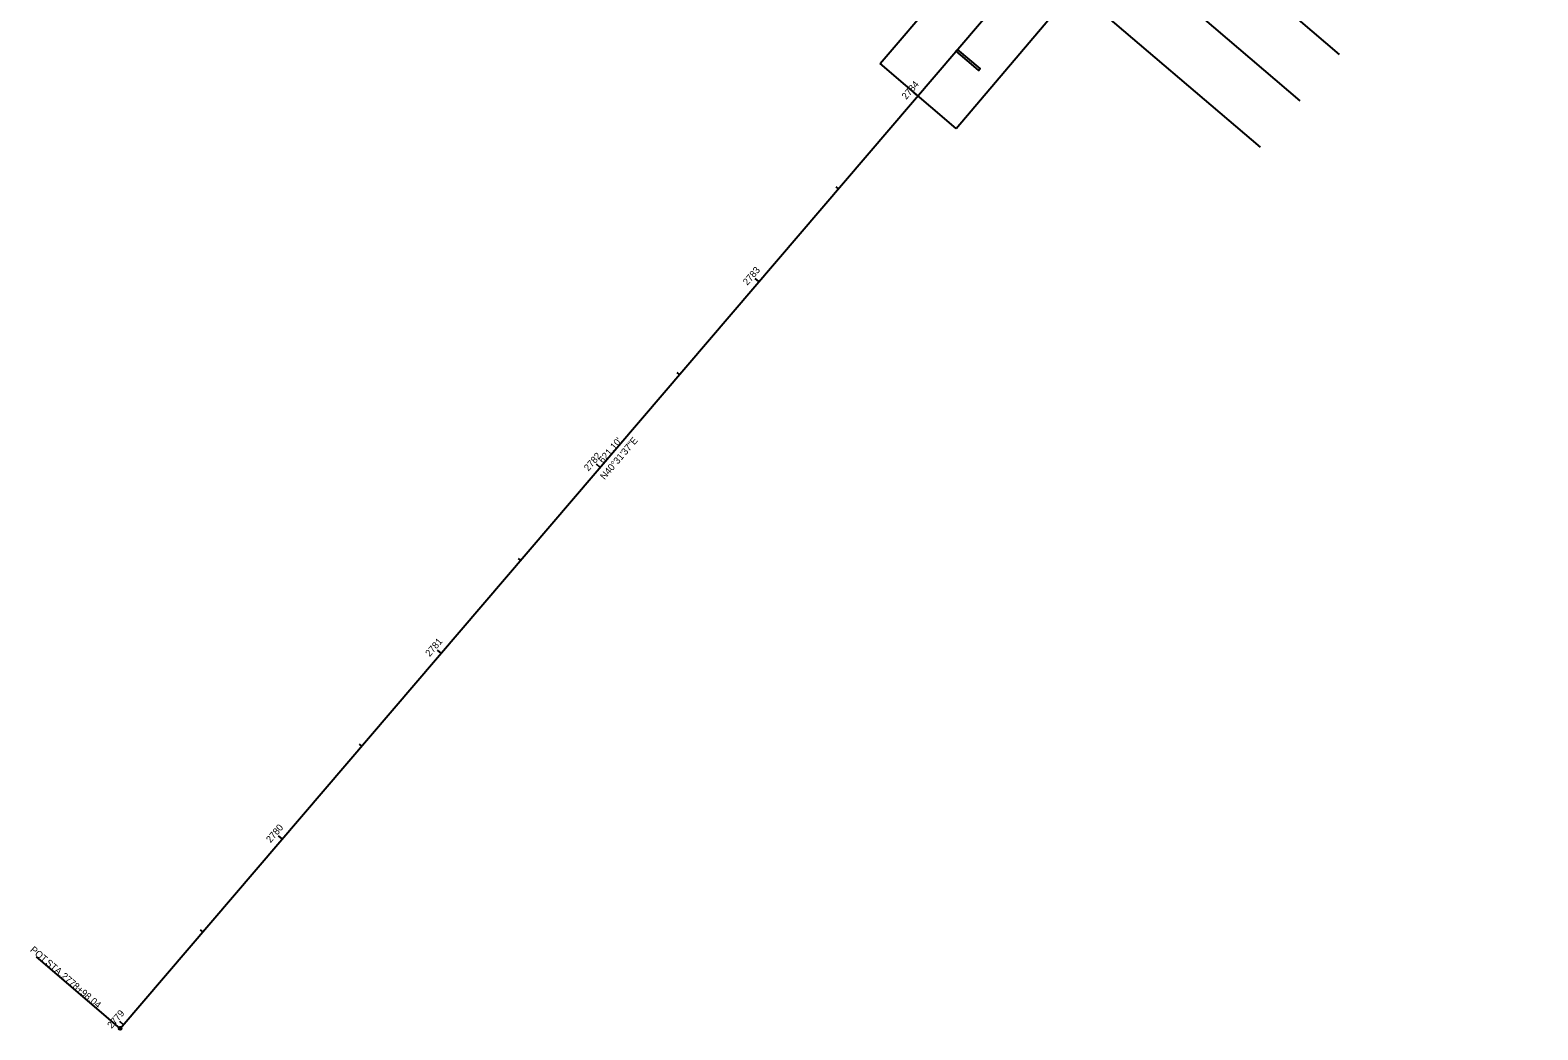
# Model space of a CAD drawing. Extents: x 2376379 to 2383101, y 559608 to 561720.
# Drawn here: x 2376379 to 2376996, y 560532 to 560941 of the extents above; entities that cross this region are included whole.
import ezdxf

# ---------------------------------------------------------------- set-up
doc = ezdxf.new("R2010")
doc.units = 0
for name, color, linetype in [('BD_X_Building', 7, 'Continuous'), ('DR_X_Elev_Flow', 7, 'Continuous'), ('DT_X_Contour_Minor', 7, 'Continuous'), ('HY_X_Spring_Cells', 7, 'Continuous'), ('PM_X_CL_Pass_Proh_Rt', 7, 'Continuous'), ('PM_X_Surveyed_Line', 7, 'Continuous'), ('PV_X_EOP', 7, 'Continuous'), ('RD_X_Cells', 7, 'Continuous')]:
    doc.layers.add(name, color=color, linetype=linetype)

msp = doc.modelspace()

# ---------------------------------------------------------------- linework, layer by layer
at = {"layer": 'DT_X_Contour_Minor'}
for p, q in [((2376726.65, 560927.31), (2376823.82, 561040.67)), ((2376757.77, 560900.7), (2376855.78, 561016.25)), ((2376757.77, 560900.7), (2376726.65, 560927.31))]:
    msp.add_line(p, q, dxfattribs=at)
at = {"layer": 'HY_X_Spring_Cells'}
msp.add_line((2376415.94, 560532.55), (2376381.73, 560561.79), dxfattribs=at)
msp.add_circle((2376415.94, 560532.55), 0.6, dxfattribs=at)
at = {"layer": 'PM_X_CL_Pass_Proh_Rt'}
msp.add_lwpolyline([(2376758.36, 560933.09), (2376757.71, 560932.33), (2376763.91, 560927.03), (2376766.91, 560924.47), (2376767.56, 560925.23)], close=True, dxfattribs=at)
at = {"layer": 'PM_X_Surveyed_Line'}
for p, q in [((2376914.48, 560931.03), (2376732.21, 561087.17)), ((2376715.88, 561068.07), (2376898.31, 560912.12)), ((2376699.64, 561049.07), (2376882.06, 560893.12))]:
    msp.add_line(p, q, dxfattribs=at)
at = {"layer": 'PV_X_EOP'}
for p, q in [((2376742.12, 560914.09), (2376740.6, 560915.39)), ((2376709.63, 560876.08), (2376708.71, 560876.86)), ((2376677.13, 560838.08), (2376675.61, 560839.38)), ((2376644.64, 560800.07), (2376643.73, 560800.85)), ((2376612.15, 560762.07), (2376610.63, 560763.37)), ((2376579.66, 560724.06), (2376578.75, 560724.84)), ((2376547.17, 560686.06), (2376545.65, 560687.35)), ((2376514.68, 560648.05), (2376513.77, 560648.83)), ((2376482.19, 560610.05), (2376480.67, 560611.34)), ((2376449.7, 560572.04), (2376448.79, 560572.82)), ((2376417.21, 560534.04), (2376415.69, 560535.33))]:
    msp.add_line(p, q, dxfattribs=at)
at = {"layer": 'RD_X_Cells'}
for q in [(2376995.66, 561210.67), (2376819.53, 561004.64)]:
    msp.add_line((2376415.94, 560532.55), q, dxfattribs=at)

# ---------------------------------------------------------------- texts
at = {"layer": 'BD_X_Building'}
msp.add_text("621.10'", height=2.8, rotation=49.47313, dxfattribs=at).set_placement((2376613.36, 560763.55))
at = {"layer": 'DR_X_Elev_Flow'}
msp.add_text('N40°31\'37"E', height=2.8, rotation=49.47313, dxfattribs=at).set_placement((2376614, 560756.84))
at = {"layer": 'HY_X_Spring_Cells'}
for s, p in [('POT', (2376378.84, 560564.31)), (' STA. ', (2376384.32, 560559.64)), ('2778+98.04', (2376391.5, 560553.49))]:
    msp.add_text(s, height=2.8, rotation=319.47313, dxfattribs=at).set_placement(p)
at = {"layer": 'PV_X_EOP'}
for s, p in [('2784', (2376737.36, 560912.37)), ('2783', (2376672.38, 560836.36)), ('2782', (2376607.4, 560760.35)), ('2781', (2376542.5, 560684.44)), ('2780', (2376477.39, 560608.28)), ('2779', (2376412.43, 560532.29))]:
    msp.add_text(s, height=2.8, rotation=49.47313, dxfattribs=at).set_placement(p)

doc.saveas('drawing.dxf')
